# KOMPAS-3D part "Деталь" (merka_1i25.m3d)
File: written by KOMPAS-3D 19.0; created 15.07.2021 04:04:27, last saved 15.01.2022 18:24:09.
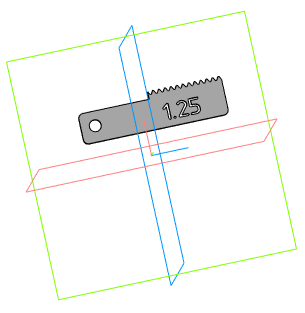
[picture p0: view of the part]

Document properties: Полное имя файла: D:\3D-Printer\Models\Для хозяйства\Сантехника\My\Мерки резьбы\merka_1i25.m3d

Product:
- Part/product: Деталь
    Масса: 0.00124682

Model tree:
1. ЛСК (Внешняя цилиндрическая ступень с метрической резьбой):1  (with: Внешняя цилиндрическая ступень с метрической резьбой:1, Плоскость XY, Плоскость ZX, Плоскость ZY, Ось X, Ось Y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)
     Ось X. Z = -1; Ось Y. X = -1; Ось Z. Y = 1; Угол 1 = 360; Угол 1 = 360; Угол 1 = 360
2. Эскиз выреза профиля резьбы (Внешняя цилиндрическая ступень с метрической резьбой):1  (with: Винтовая линия (Внешняя цилиндрическая ступень с метрической резьбой):1)
     Расстояние = 20; Число витков = 16; Шаг = 1.25; Высота = 20; Диаметр 1 = 26; Диаметр 2 = 10; Угол = 270; Число витков = 2.5; Шаг = 1.25; Высота = 3.125; Диаметр 1 = 26; Диаметр 2 = 28.5252; Угол наклона образующей = 22; Угол = 270
3. Внешняя цилиндрическая ступень с метрической резьбой:1
4. Эскиз:15  (with: Цилиндр (Внешняя цилиндрическая ступень с метрической резьбой):1)
5. Элемент выдавливания:3
     Расстояние 2 = 2
6. Эскиз:16  (with: Цилиндр (Внешняя цилиндрическая ступень с метрической резьбой):1, Фаска (Внешняя цилиндрическая ступень с метрической резьбой):1)
7. Элемент выдавливания:4
     Расстояние 2 = 2
8. Эскиз:17
9. Элемент выдавливания:6
     Расстояние 1 = 18
10. Эскиз:18  (with: Элемент выдавливания:3)
11. Элемент выдавливания:7
     Расстояние 2 = 16
12. Цифра мерки  (with: Элемент выдавливания:7)
13. Элемент выдавливания:8
     Расстояние 2 = 0.8
14. Эскиз:20  (with: Элемент выдавливания:7)
15. Элемент выдавливания:9
     Расстояние 2 = 0.8
16. Эскиз:21  (with: Элемент выдавливания:3, Элемент выдавливания:7)
17. Элемент выдавливания:10
     Расстояние 1 = 15
18. Скругление:2  (with: Элемент выдавливания:9, Элемент выдавливания:10)
     Радиус = 1
19. Эскиз:22  (with: Элемент выдавливания:7, Элемент выдавливания:10)
20. Элемент выдавливания:11

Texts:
  [Data]  D=26  L=20  Len_Th=20  Step=1.25  Tip_Step=2  PoleTh=[6g]  Flag_Left_Thread=2  ExistThrough=0  TypeThrough=1  SubType=0  DiamF=0  Flag_FaskOnGOST=1  Fask=1.6  FAngle=45  F=4  R=1  R1=0.5  R2=0  Df=1.8  Flag_NoStandart=1  NS_Prototype=0  NTDThrough=0  MarkRing=не выбрано  MarkThread=М26x1,25-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
  SHAFT3D
  (VCThMetrO_1_D<=0||VCThMetrO_1_D>5e+7)?25:VCThMetrO_1_D
  (VCThMetrO_1_L<=0||VCThMetrO_1_L>5e+7)?25:VCThMetrO_1_L
  Плоскость начала спирали резьбы (Внешняя цилиндрическая ступень с метрической резьбой):1
  Эскиз для винтовой линии (Внешняя цилиндрическая ступень с метрической резьбой):1
  Плоскость начала конической спирали резьбы (Внешняя цилиндрическая ступень с метрической резьбой):1
  Коническая винтовая линия (Внешняя цилиндрическая ступень с метрической резьбой):1
  Вырез профиля резьбы (Внешняя цилиндрическая ступень с метрической резьбой):1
